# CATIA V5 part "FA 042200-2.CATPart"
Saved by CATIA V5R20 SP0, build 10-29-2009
Part number: FA 042200-2
Revision: ANY
Definition: UNKNOWN
Nomenclature: FA 042200-2
Source: Unknown
Bounding box of the stored display mesh (mm): x -1.5 to 1.5, y 0 to 3.7, z -1.5 to 1.5
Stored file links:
  C:\Users\Utente\Desktop\IO LAVORO\3D X SITO CF\CUMSA\3D files FA\FA 0422SF\FA 042200-2.CATPart

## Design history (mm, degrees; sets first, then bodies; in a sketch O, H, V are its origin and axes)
Body1 "Cortar-Extruir1" (main body)
  Solid1: solid without history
